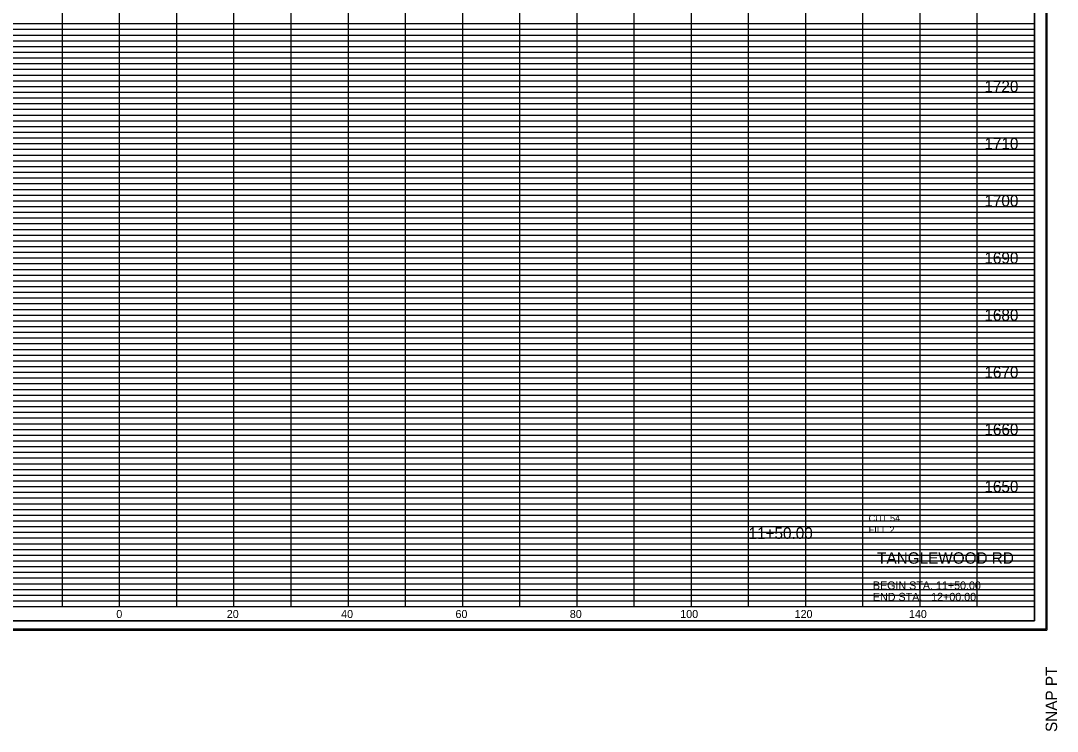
# Model space of a CAD drawing. Extents: x 980 to 1324, y 978 to 1497.
# Drawn here: x 1142.7 to 1324, y 1248.2 to 1372.5 of the extents above; entities that cross this region are included whole.
import ezdxf

# ---------------------------------------------------------------- set-up
doc = ezdxf.new("R2010")
doc.units = 0
for name, color, linetype in [('DESIGN - SHEET - Corner Text', 7, 'Continuous'), ('DESIGN - SHEET - Light Grid', 7, 'Continuous'), ('DESIGN - SHEET - Linework', 7, 'Continuous'), ('DESIGN - SHEET - Plot Shape', 7, 'Continuous'), ('DESIGN - TYPICAL - Finished Grade and Subgrade', 7, 'Continuous'), ('DESIGN - TYPICAL - Text', 7, 'Continuous')]:
    doc.layers.add(name, color=color, linetype=linetype)

# ---------------------------------------------------------------- blocks, each defined once
blk = doc.blocks.new('XSTSHT')
at = {"layer": 'DESIGN - SHEET - Light Grid'}
for p, q in [((8, 10.2), (16, 10.2)), ((16, 10.2), (24, 10.2)), ((24, 10.2), (32, 10.2)), ((8, 10.1), (16, 10.1)), ((16, 10.1), (24, 10.1)), ((24, 10.1), (32, 10.1)), ((8, 9.9), (16, 9.9)), ((8, 9.8), (16, 9.8)), ((16, 9.9), (24, 9.9)), ((16, 9.8), (24, 9.8)), ((24, 9.9), (32, 9.9)), ((24, 9.8), (32, 9.8)), ((8, 9.7), (16, 9.7)), ((16, 9.7), (24, 9.7)), ((24, 9.7), (32, 9.7)), ((8, 9.6), (16, 9.6)), ((8, 9.5), (16, 9.5)), ((16, 9.6), (24, 9.6)), ((16, 9.5), (24, 9.5)), ((24, 9.6), (32, 9.6)), ((24, 9.5), (32, 9.5)), ((8, 9.4), (16, 9.4)), ((8, 9.3), (16, 9.3)), ((16, 9.4), (24, 9.4)), ((16, 9.3), (24, 9.3)), ((24, 9.4), (32, 9.4)), ((24, 9.3), (32, 9.3)), ((8, 9.2), (16, 9.2)), ((8, 9.1), (16, 9.1)), ((16, 9.2), (24, 9.2)), ((16, 9.1), (24, 9.1)), ((24, 9.2), (32, 9.2)), ((24, 9.1), (32, 9.1)), ((8, 8.9), (16, 8.9)), ((16, 8.9), (24, 8.9)), ((24, 8.9), (32, 8.9)), ((8, 8.8), (16, 8.8)), ((16, 8.8), (24, 8.8)), ((24, 8.8), (32, 8.8)), ((8, 8.7), (16, 8.7)), ((8, 8.6), (16, 8.6)), ((16, 8.7), (24, 8.7)), ((16, 8.6), (24, 8.6)), ((24, 8.7), (32, 8.7)), ((24, 8.6), (32, 8.6)), ((8, 8.5), (16, 8.5)), ((8, 8.4), (16, 8.4)), ((16, 8.5), (24, 8.5)), ((16, 8.4), (24, 8.4)), ((24, 8.5), (32, 8.5)), ((24, 8.4), (32, 8.4)), ((8, 8.3), (16, 8.3)), ((8, 8.2), (16, 8.2)), ((16, 8.3), (24, 8.3)), ((16, 8.2), (24, 8.2)), ((24, 8.3), (32, 8.3)), ((24, 8.2), (32, 8.2)), ((8, 8.1), (16, 8.1)), ((16, 8.1), (24, 8.1)), ((24, 8.1), (32, 8.1)), ((8, 7.9), (16, 7.9)), ((8, 7.8), (16, 7.8)), ((16, 7.9), (24, 7.9)), ((16, 7.8), (24, 7.8)), ((24, 7.9), (32, 7.9)), ((24, 7.8), (32, 7.8)), ((8, 7.7), (16, 7.7)), ((16, 7.7), (24, 7.7)), ((24, 7.7), (32, 7.7)), ((8, 7.6), (16, 7.6)), ((8, 7.5), (16, 7.5)), ((16, 7.6), (24, 7.6)), ((16, 7.5), (24, 7.5)), ((24, 7.6), (32, 7.6)), ((24, 7.5), (32, 7.5)), ((8, 7.4), (16, 7.4)), ((8, 7.3), (16, 7.3)), ((16, 7.4), (24, 7.4)), ((16, 7.3), (24, 7.3)), ((24, 7.4), (32, 7.4)), ((24, 7.3), (32, 7.3)), ((8, 7.2), (16, 7.2)), ((8, 7.1), (16, 7.1)), ((16, 7.2), (24, 7.2)), ((16, 7.1), (24, 7.1)), ((24, 7.2), (32, 7.2)), ((24, 7.1), (32, 7.1)), ((8, 6.9), (16, 6.9)), ((16, 6.9), (24, 6.9)), ((24, 6.9), (32, 6.9)), ((8, 6.8), (16, 6.8)), ((16, 6.8), (24, 6.8)), ((24, 6.8), (32, 6.8)), ((8, 6.7), (16, 6.7)), ((8, 6.6), (16, 6.6)), ((16, 6.7), (24, 6.7)), ((16, 6.6), (24, 6.6)), ((24, 6.7), (32, 6.7)), ((24, 6.6), (32, 6.6)), ((8, 6.5), (16, 6.5)), ((8, 6.4), (16, 6.4)), ((16, 6.5), (24, 6.5)), ((16, 6.4), (24, 6.4)), ((24, 6.5), (32, 6.5)), ((24, 6.4), (32, 6.4)), ((8, 6.3), (16, 6.3)), ((8, 6.2), (16, 6.2)), ((16, 6.3), (24, 6.3)), ((16, 6.2), (24, 6.2)), ((24, 6.3), (32, 6.3)), ((24, 6.2), (32, 6.2)), ((8, 6.1), (16, 6.1)), ((16, 6.1), (24, 6.1)), ((24, 6.1), (32, 6.1)), ((8, 5.9), (16, 5.9)), ((16, 5.9), (24, 5.9)), ((24, 5.9), (32, 5.9)), ((8, 5.8), (16, 5.8)), ((8, 5.7), (16, 5.7)), ((16, 5.8), (24, 5.8)), ((16, 5.7), (24, 5.7)), ((24, 5.8), (32, 5.8)), ((24, 5.7), (32, 5.7)), ((8, 5.6), (16, 5.6)), ((8, 5.5), (16, 5.5)), ((16, 5.6), (24, 5.6)), ((16, 5.5), (24, 5.5)), ((24, 5.6), (32, 5.6)), ((24, 5.5), (32, 5.5)), ((8, 5.4), (16, 5.4)), ((8, 5.3), (16, 5.3)), ((16, 5.4), (24, 5.4)), ((16, 5.3), (24, 5.3)), ((24, 5.4), (32, 5.4)), ((24, 5.3), (32, 5.3)), ((8, 5.2), (16, 5.2)), ((8, 5.1), (16, 5.1)), ((16, 5.2), (24, 5.2)), ((16, 5.1), (24, 5.1)), ((24, 5.2), (32, 5.2)), ((24, 5.1), (32, 5.1)), ((8, 4.9), (16, 4.9)), ((16, 4.9), (24, 4.9)), ((24, 4.9), (32, 4.9)), ((8, 4.8), (16, 4.8)), ((16, 4.8), (24, 4.8)), ((24, 4.8), (32, 4.8)), ((8, 4.7), (16, 4.7)), ((8, 4.6), (16, 4.6)), ((16, 4.7), (24, 4.7)), ((16, 4.6), (24, 4.6)), ((24, 4.7), (32, 4.7)), ((24, 4.6), (32, 4.6)), ((8, 4.5), (16, 4.5)), ((8, 4.4), (16, 4.4)), ((16, 4.5), (24, 4.5)), ((16, 4.4), (24, 4.4)), ((24, 4.5), (32, 4.5)), ((24, 4.4), (32, 4.4)), ((8, 4.3), (16, 4.3)), ((8, 4.2), (16, 4.2)), ((16, 4.3), (24, 4.3)), ((16, 4.2), (24, 4.2)), ((24, 4.3), (32, 4.3)), ((24, 4.2), (32, 4.2)), ((8, 4.1), (16, 4.1)), ((16, 4.1), (24, 4.1)), ((24, 4.1), (32, 4.1)), ((8, 3.9), (16, 3.9)), ((16, 3.9), (24, 3.9)), ((24, 3.9), (32, 3.9)), ((8, 3.8), (16, 3.8)), ((8, 3.7), (16, 3.7)), ((16, 3.8), (24, 3.8)), ((16, 3.7), (24, 3.7)), ((24, 3.8), (32, 3.8)), ((24, 3.7), (32, 3.7)), ((8, 3.6), (16, 3.6)), ((8, 3.5), (16, 3.5)), ((16, 3.6), (24, 3.6)), ((16, 3.5), (24, 3.5)), ((24, 3.6), (32, 3.6)), ((24, 3.5), (32, 3.5)), ((8, 3.4), (16, 3.4)), ((8, 3.3), (16, 3.3)), ((16, 3.4), (24, 3.4)), ((16, 3.3), (24, 3.3)), ((24, 3.4), (32, 3.4)), ((24, 3.3), (32, 3.3)), ((8, 3.2), (16, 3.2)), ((8, 3.1), (16, 3.1)), ((16, 3.2), (24, 3.2)), ((16, 3.1), (24, 3.1)), ((24, 3.2), (32, 3.2)), ((24, 3.1), (32, 3.1)), ((8, 2.9), (16, 2.9)), ((8, 2.8), (16, 2.8)), ((16, 2.9), (24, 2.9)), ((16, 2.8), (24, 2.8)), ((24, 2.9), (32, 2.9)), ((24, 2.8), (32, 2.8)), ((8, 2.7), (16, 2.7)), ((8, 2.6), (16, 2.6)), ((16, 2.7), (24, 2.7)), ((16, 2.6), (24, 2.6)), ((24, 2.7), (32, 2.7)), ((24, 2.6), (32, 2.6)), ((8, 2.5), (16, 2.5)), ((8, 2.4), (16, 2.4)), ((16, 2.5), (24, 2.5)), ((16, 2.4), (24, 2.4)), ((24, 2.5), (32, 2.5)), ((24, 2.4), (32, 2.4)), ((8, 2.3), (16, 2.3)), ((8, 2.2), (16, 2.2)), ((16, 2.3), (24, 2.3)), ((16, 2.2), (24, 2.2)), ((24, 2.3), (32, 2.3)), ((24, 2.2), (32, 2.2)), ((8, 2.1), (16, 2.1)), ((16, 2.1), (24, 2.1)), ((24, 2.1), (32, 2.1)), ((8, 1.9), (16, 1.9)), ((16, 1.9), (24, 1.9)), ((24, 1.9), (32, 1.9)), ((8, 1.8), (16, 1.8)), ((8, 1.7), (16, 1.7)), ((16, 1.8), (24, 1.8)), ((16, 1.7), (24, 1.7)), ((24, 1.8), (32, 1.8)), ((24, 1.7), (32, 1.7)), ((8, 1.6), (16, 1.6)), ((8, 1.5), (16, 1.5)), ((16, 1.6), (24, 1.6)), ((16, 1.5), (24, 1.5)), ((24, 1.6), (32, 1.6)), ((24, 1.5), (32, 1.5)), ((8, 1.4), (16, 1.4)), ((8, 1.3), (16, 1.3)), ((16, 1.4), (24, 1.4)), ((16, 1.3), (24, 1.3)), ((24, 1.4), (32, 1.4)), ((24, 1.3), (32, 1.3)), ((8, 1.2), (16, 1.2)), ((8, 1.1), (16, 1.1)), ((16, 1.2), (24, 1.2)), ((16, 1.1), (24, 1.1)), ((24, 1.2), (32, 1.2)), ((24, 1.1), (32, 1.1)), ((8, 0.9), (16, 0.9)), ((8, 0.8), (16, 0.8)), ((16, 0.9), (24, 0.9)), ((16, 0.8), (24, 0.8)), ((24, 0.9), (32, 0.9)), ((24, 0.8), (32, 0.8)), ((8, 0.7), (16, 0.7)), ((8, 0.6), (16, 0.6)), ((16, 0.7), (24, 0.7)), ((16, 0.6), (24, 0.6)), ((24, 0.7), (32, 0.7)), ((24, 0.6), (32, 0.6)), ((8, 0.5), (16, 0.5)), ((8, 0.4), (16, 0.4)), ((16, 0.5), (24, 0.5)), ((16, 0.4), (24, 0.4)), ((24, 0.5), (32, 0.5)), ((24, 0.4), (32, 0.4)), ((8, 0.3), (16, 0.3)), ((8, 0.2), (16, 0.2)), ((16, 0.3), (24, 0.3)), ((16, 0.2), (24, 0.2)), ((24, 0.3), (32, 0.3)), ((24, 0.2), (32, 0.2)), ((8, 0.1), (16, 0.1)), ((16, 0.1), (24, 0.1)), ((24, 0.1), (32, 0.1))]:
    blk.add_line(p, q, dxfattribs=at)
at = {"layer": 'DESIGN - SHEET - Linework'}
for p, q in [((32.217, 21.414), (32.217, -0.414)), ((15, 0), (15, 21)), ((16, 0), (16, 21)), ((17, 0), (17, 21)), ((18, 0), (18, 21)), ((19, 0), (19, 21)), ((20, 0), (20, 21)), ((21, 0), (21, 21)), ((22, 0), (22, 21)), ((23, 0), (23, 21)), ((24, 0), (24, 21)), ((25, 0), (25, 21)), ((26, 0), (26, 21)), ((27, 0), (27, 21)), ((28, 0), (28, 20)), ((29, 0), (29, 20)), ((30, 0), (30, 20)), ((31, 0), (31, 20)), ((0, 10), (32, 10)), ((0, 9), (32, 9)), ((0, 8), (32, 8)), ((0, 7), (32, 7)), ((0, 6), (32, 6)), ((0, 5), (32, 5)), ((0, 4), (32, 4)), ((0, 3), (32, 3)), ((0, 2), (32, 2)), ((0, 1), (32, 1)), ((-1.823, -0.414), (32.217, -0.414))]:
    blk.add_line(p, q, dxfattribs=at)
blk.add_lwpolyline([(0, 21), (0, 0), (32, 0), (32, 21), (0, 21)], dxfattribs=at)
at = {"layer": 'DESIGN - SHEET - Plot Shape'}
for points in [[(-1.803, 21.394), (32.197, 21.394), (32.197, -0.394), (-1.803, -0.394)], [(-0.85, 21), (32, 21), (32, -0.25), (-0.85, -0.25)]]:
    blk.add_lwpolyline(points, close=True, dxfattribs=at)
at = {"layer": 'DESIGN - SHEET - Corner Text'}
blk.add_text('SNAP PT  ', height=0.2, rotation=90, dxfattribs=at).set_placement((32.397, -2.194))

msp = doc.modelspace()

# ---------------------------------------------------------------- linework, layer by layer
at = {"layer": 'DESIGN - SHEET - Plot Shape'}
msp.add_lwpolyline([(991.5, 1267.5), (1320, 1267.5), (1320, 1480), (991.5, 1480)], close=True, dxfattribs=at)

# ---------------------------------------------------------------- block references
at = {"layer": 'DESIGN - TYPICAL - Finished Grade and Subgrade', "xscale": 10, "yscale": 10}
msp.add_blockref('XSTSHT', (1000, 1270), dxfattribs=at)

# ---------------------------------------------------------------- texts
at = {"layer": 'DESIGN - SHEET - Corner Text'}
for s, height, p in [('1720', 2, (1311.25, 1360)), ('1710', 2, (1311.25, 1350)), ('1700', 2, (1311.25, 1340)), ('1690', 2, (1311.25, 1330)), ('1680', 2, (1311.25, 1320)), ('1670', 2, (1311.25, 1310)), ('1660', 2, (1311.25, 1300)), ('1650', 2, (1311.25, 1290)), ('11+50.00', 2, (1270, 1281.85)), ('TANGLEWOOD RD', 2, (1292.49, 1277.5)), ('BEGIN STA. 11+50.00', 1.4, (1291.75, 1273)), ('END STA.   12+00.00', 1.4, (1291.75, 1271)), ('0', 1.4, (1159.42, 1268)), ('0', 1.4, (1159.42, 1268)), ('20', 1.4, (1178.74, 1268)), ('40', 1.4, (1198.74, 1268)), ('60', 1.4, (1218.74, 1268)), ('80', 1.4, (1238.74, 1268)), ('100', 1.4, (1258.06, 1268)), ('120', 1.4, (1278.06, 1268)), ('140', 1.4, (1298.06, 1268))]:
    msp.add_text(s, height=height, dxfattribs=at).set_placement(p)
at = {"layer": 'DESIGN - TYPICAL - Text'}
for s, p in [('CUT 54', (1291, 1284.85)), ('FILL 2', (1291, 1282.85))]:
    msp.add_text(s, height=1.2, dxfattribs=at).set_placement(p)

doc.saveas('drawing.dxf')
